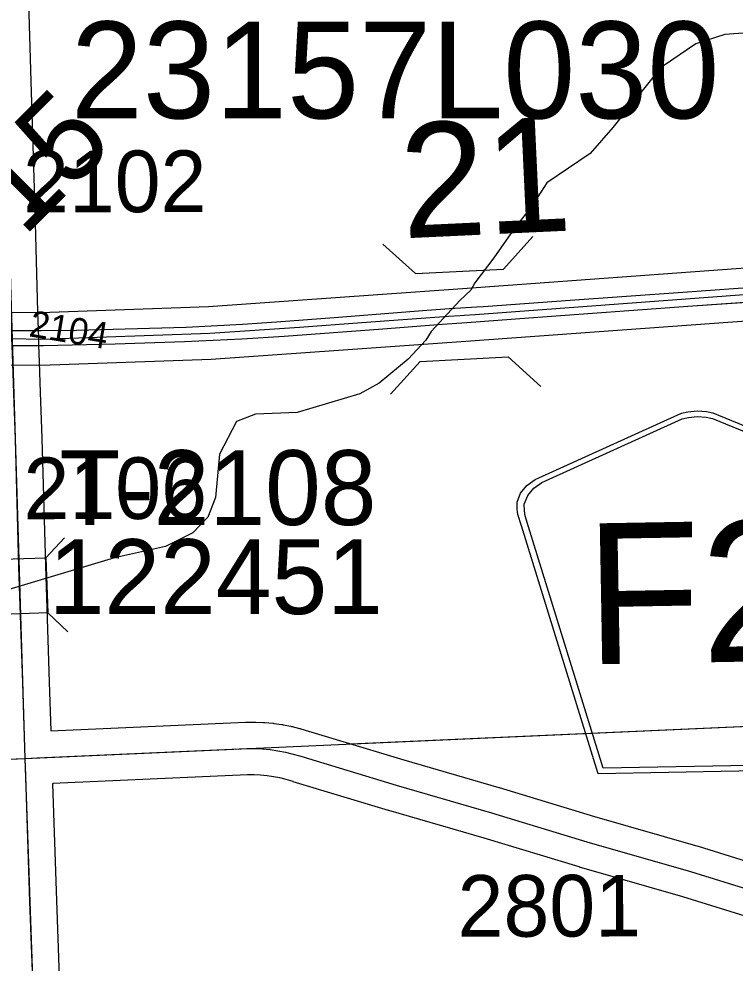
# Model space of a CAD drawing. Extents: x 128.7 to 185.5, y -21.4 to 12.6.
# Drawn here: x 154.302 to 155.116, y -11.291 to -10.218 of the extents above; entities that cross this region are included whole.
import ezdxf

# ---------------------------------------------------------------- set-up
doc = ezdxf.new("R2010")
doc.units = 0
for name, color, linetype in [('tdCoDivCarto', 7, 'Continuous'), ('tdCoHydroRiver', 7, 'Continuous'), ('tdCoPriCL', 7, 'Continuous'), ('tdCoPriDiv', 7, 'Continuous'), ('tdCoPrimary', 7, 'Continuous'), ('tdCoSecRdNmbr', 7, 'Continuous'), ('tdCoSecRteBand', 7, 'Continuous'), ('tdCoSecRteCL', 7, 'Continuous'), ('tdCoSectLine', 7, 'Continuous'), ('tdCoSectLinePart', 7, 'Continuous'), ('tdCoSectNmbr', 7, 'Continuous'), ('tdCoShieldCoRte', 7, 'Continuous'), ('tdCoStrucDivPri', 7, 'Continuous'), ('tdCoStrucPriMaintName', 7, 'Continuous'), ('tdCoStrucSec', 7, 'Continuous'), ('tdCoStrucSecCoName', 7, 'Continuous'), ('tdCoStrucSecFHWANum', 7, 'Continuous'), ('tdCoSurfAsphalt', 7, 'Continuous'), ('tdCoSurfGravel', 7, 'Continuous'), ('tdStHwyPriRefPost1', 7, 'Continuous'), ('tdStHwyPriRefPost5', 7, 'Continuous')]:
    doc.layers.add(name, color=color, linetype=linetype)

msp = doc.modelspace()

# ---------------------------------------------------------------- linework, layer by layer
at = {"layer": 'tdCoDivCarto'}
for p, q in [((155.0563, -10.5289), (154.9283, -10.538)), ((155.1189, -10.5245), (155.0563, -10.5289)), ((154.9283, -10.538), (154.8299, -10.5452)), ((155.0673, -10.5444), (155.1485, -10.5385)), ((154.7656, -10.5496), (154.6603, -10.5577)), ((154.7914, -10.5478), (154.7656, -10.5496)), ((154.8222, -10.5457), (154.7914, -10.5478)), ((154.8299, -10.5452), (154.8222, -10.5457)), ((154.8814, -10.5577), (155.0673, -10.5444)), ((154.5947, -10.5627), (154.5562, -10.5656)), ((154.6603, -10.5577), (154.5947, -10.5627)), ((154.7831, -10.5652), (154.8111, -10.5631)), ((154.8111, -10.5631), (154.8814, -10.5577)), ((154.3275, -10.5725), (154.2942, -10.5726)), ((154.3275, -10.5725), (154.2942, -10.5726)), ((154.3678, -10.5723), (154.3275, -10.5725)), ((154.4921, -10.5688), (154.3678, -10.5723)), ((154.5562, -10.5656), (154.4921, -10.5688)), ((154.6035, -10.5785), (154.7154, -10.5703)), ((154.7154, -10.5703), (154.7831, -10.5652)), ((154.4116, -10.5873), (154.4905, -10.5849)), ((154.4905, -10.5849), (154.5554, -10.5817)), ((154.5554, -10.5817), (154.6035, -10.5785)), ((154.2948, -10.5893), (154.3275, -10.5893)), ((154.2948, -10.5893), (154.3275, -10.5893)), ((154.3275, -10.5893), (154.3302, -10.5893)), ((154.3302, -10.5893), (154.4116, -10.5873))]:
    msp.add_line(p, q, dxfattribs=at)
for points in [[(155.4926, -10.4959), (155.4839, -10.4966), (155.4307, -10.5003), (155.3806, -10.5042), (155.3357, -10.5082), (155.2247, -10.5163), (155.1897, -10.5198), (155.1189, -10.5245), (155.0563, -10.5289), (154.9283, -10.538), (154.8299, -10.5452), (154.8222, -10.5457), (154.7914, -10.5478), (154.7656, -10.5496), (154.6603, -10.5577), (154.5947, -10.5627), (154.5562, -10.5656), (154.4921, -10.5688), (154.3678, -10.5723), (154.3275, -10.5725)], [(155.4926, -10.4959), (155.4839, -10.4966), (155.4307, -10.5003), (155.3806, -10.5042), (155.3357, -10.5082), (155.2247, -10.5163), (155.1897, -10.5198), (155.1189, -10.5245), (155.0563, -10.5289), (154.9283, -10.538), (154.8299, -10.5452), (154.8222, -10.5457), (154.7914, -10.5478), (154.7656, -10.5496), (154.6603, -10.5577), (154.5947, -10.5627), (154.5562, -10.5656), (154.4921, -10.5688), (154.3678, -10.5723), (154.3275, -10.5725)], [(155.4926, -10.4959), (155.4839, -10.4966), (155.4307, -10.5003), (155.3806, -10.5042), (155.3357, -10.5082), (155.2247, -10.5163), (155.1897, -10.5198), (155.1189, -10.5245), (155.0563, -10.5289), (154.9283, -10.538), (154.8299, -10.5452), (154.8222, -10.5457), (154.7914, -10.5478), (154.7656, -10.5496), (154.6603, -10.5577), (154.5947, -10.5627), (154.5562, -10.5656), (154.4921, -10.5688), (154.3678, -10.5723), (154.3275, -10.5725)], [(154.3275, -10.5893), (154.3302, -10.5893), (154.4116, -10.5873), (154.4905, -10.5849), (154.5554, -10.5817), (154.6035, -10.5785), (154.7154, -10.5703), (154.7831, -10.5652), (154.8111, -10.5631), (154.8814, -10.5577), (155.0673, -10.5444), (155.1485, -10.5385), (155.2893, -10.5274), (155.4414, -10.5161), (155.4939, -10.5119)], [(154.3275, -10.5893), (154.3302, -10.5893), (154.4116, -10.5873), (154.4905, -10.5849), (154.5554, -10.5817), (154.6035, -10.5785), (154.7154, -10.5703), (154.7831, -10.5652), (154.8111, -10.5631), (154.8814, -10.5577), (155.0673, -10.5444), (155.1485, -10.5385), (155.2893, -10.5274), (155.4414, -10.5161), (155.4939, -10.5119)], [(154.3275, -10.5893), (154.3302, -10.5893), (154.4116, -10.5873), (154.4905, -10.5849), (154.5554, -10.5817), (154.6035, -10.5785), (154.7154, -10.5703), (154.7831, -10.5652), (154.8111, -10.5631), (154.8814, -10.5577), (155.0673, -10.5444), (155.1485, -10.5385), (155.2893, -10.5274), (155.4414, -10.5161), (155.4939, -10.5119)], [(154.3275, -10.5725), (154.2942, -10.5726)], [(154.3275, -10.5725), (154.2942, -10.5726)], [(154.2948, -10.5893), (154.3275, -10.5893)], [(154.2948, -10.5893), (154.3275, -10.5893)]]:
    msp.add_lwpolyline(points, dxfattribs=at)
at = {"layer": 'tdCoHydroRiver'}
msp.add_lwpolyline([(155.1401, -10.2333), (155.1039, -10.2362), (155.0711, -10.2468), (155.0341, -10.2718), (155.022, -10.2849), (154.9767, -10.3417), (154.9509, -10.3711), (154.9016, -10.4044), (154.8847, -10.431), (154.8661, -10.4545), (154.8415, -10.4896), (154.8199, -10.5181), (154.8153, -10.5264), (154.8028, -10.5383), (154.7704, -10.5734), (154.7643, -10.5832), (154.7442, -10.6049), (154.7115, -10.632), (154.6896, -10.6443), (154.6184, -10.6655), (154.5711, -10.6671), (154.5493, -10.6757), (154.5301, -10.7127), (154.5255, -10.7618), (154.5168, -10.7842), (154.5, -10.8021), (154.469, -10.8174), (154.411, -10.8304), (154.286, -10.8678)], dxfattribs=at)
at = {"layer": 'tdCoPriCL'}
msp.add_lwpolyline([(153.0442, -10.649), (153.1163, -10.643), (153.1776, -10.6373), (153.2928, -10.6269), (153.3089, -10.6255), (153.3454, -10.6224), (153.5843, -10.6023), (153.6845, -10.5941), (153.9006, -10.5841), (154.0396, -10.5816), (154.0415, -10.5816), (154.0437, -10.5816), (154.0641, -10.5812), (154.2274, -10.5809), (154.2935, -10.5813), (154.3272, -10.582), (154.519, -10.5753), (154.621, -10.5686), (154.6919, -10.5631), (154.79, -10.556), (154.8035, -10.5551), (154.8079, -10.5548), (154.8203, -10.5539), (155.2987, -10.5184)], dxfattribs=at)
at = {"layer": 'tdCoPriDiv'}
for points in [[(156.3051, -10.3234), (156.1332, -10.3967), (156.0515, -10.4224), (155.9864, -10.4355), (155.5871, -10.4668), (155.5413, -10.4713), (154.8061, -10.5249), (154.5175, -10.5454), (154.327, -10.552), (154.0638, -10.5512), (153.8996, -10.5541), (153.6825, -10.5641), (153.3063, -10.5956), (153.0365, -10.6196)], [(156.3288, -10.3785), (156.1544, -10.4529), (156.0668, -10.4804), (155.9958, -10.4947), (155.5922, -10.5266), (155.5457, -10.5312), (154.8098, -10.5848), (154.5205, -10.6053), (154.3274, -10.612), (154.0644, -10.6112), (153.9015, -10.6141), (153.6864, -10.624), (153.3115, -10.6554), (153.0414, -10.6794)]]:
    msp.add_lwpolyline(points, dxfattribs=at)
at = {"layer": 'tdCoPrimary'}
for p, q in [((154.3275, -10.5725), (154.2942, -10.5726)), ((154.3275, -10.5725), (154.2942, -10.5726)), ((154.2948, -10.5893), (154.3275, -10.5893)), ((154.2948, -10.5893), (154.3275, -10.5893))]:
    msp.add_line(p, q, dxfattribs=at)
for points in [[(155.4926, -10.4959), (155.4839, -10.4966), (155.4307, -10.5003), (155.3806, -10.5042), (155.3357, -10.5082), (155.2247, -10.5163), (155.1897, -10.5198), (155.1189, -10.5245), (155.0563, -10.5289), (154.9283, -10.538), (154.8299, -10.5452), (154.8222, -10.5457), (154.7914, -10.5478), (154.7656, -10.5496), (154.6603, -10.5577), (154.5947, -10.5627), (154.5562, -10.5656), (154.4921, -10.5688), (154.3678, -10.5723), (154.3275, -10.5725)], [(155.4926, -10.4959), (155.4839, -10.4966), (155.4307, -10.5003), (155.3806, -10.5042), (155.3357, -10.5082), (155.2247, -10.5163), (155.1897, -10.5198), (155.1189, -10.5245), (155.0563, -10.5289), (154.9283, -10.538), (154.8299, -10.5452), (154.8222, -10.5457), (154.7914, -10.5478), (154.7656, -10.5496), (154.6603, -10.5577), (154.5947, -10.5627), (154.5562, -10.5656), (154.4921, -10.5688), (154.3678, -10.5723), (154.3275, -10.5725)], [(154.3275, -10.5893), (154.3302, -10.5893), (154.4116, -10.5873), (154.4905, -10.5849), (154.5554, -10.5817), (154.6035, -10.5785), (154.7154, -10.5703), (154.7831, -10.5652), (154.8111, -10.5631), (154.8814, -10.5577), (155.0673, -10.5444), (155.1485, -10.5385), (155.2893, -10.5274), (155.4414, -10.5161), (155.4939, -10.5119)], [(154.3275, -10.5893), (154.3302, -10.5893), (154.4116, -10.5873), (154.4905, -10.5849), (154.5554, -10.5817), (154.6035, -10.5785), (154.7154, -10.5703), (154.7831, -10.5652), (154.8111, -10.5631), (154.8814, -10.5577), (155.0673, -10.5444), (155.1485, -10.5385), (155.2893, -10.5274), (155.4414, -10.5161), (155.4939, -10.5119)], [(155.1189, -10.5245), (155.0563, -10.5289), (154.9283, -10.538), (154.8299, -10.5452), (154.8222, -10.5457), (154.7914, -10.5478), (154.7656, -10.5496), (154.6603, -10.5577), (154.5947, -10.5627), (154.5562, -10.5656), (154.4921, -10.5688), (154.3678, -10.5723), (154.3275, -10.5725), (154.2942, -10.5726)], [(154.2948, -10.5893), (154.3275, -10.5893), (154.3302, -10.5893), (154.4116, -10.5873), (154.4905, -10.5849), (154.5554, -10.5817), (154.6035, -10.5785), (154.7154, -10.5703), (154.7831, -10.5652), (154.8111, -10.5631), (154.8814, -10.5577), (155.0673, -10.5444), (155.1485, -10.5385)]]:
    msp.add_lwpolyline(points, dxfattribs=at)
at = {"layer": 'tdCoSecRteBand'}
for points in [[(154.3114, -10.1355), (154.3161, -10.2891), (154.3161, -10.2891), (154.3161, -10.2891), (154.3203, -10.4356), (154.3203, -10.4356), (154.3203, -10.4356), (154.3235, -10.5509), (154.3242, -10.5715), (154.3245, -10.5802), (154.3248, -10.5883), (154.3255, -10.6081), (154.3255, -10.6082), (154.3255, -10.6082), (154.3255, -10.6082), (154.3267, -10.6428), (154.3267, -10.6428), (154.3267, -10.6428), (154.3284, -10.6946), (154.3284, -10.6947), (154.3284, -10.6948), (154.3324, -10.8397), (154.3368, -10.9716), (154.3368, -10.9716), (154.3368, -10.9716), (154.3386, -11.0269), (154.5598, -11.0171), (154.5604, -11.0171), (154.5609, -11.0171), (154.5698, -11.017), (154.5706, -11.017), (154.5713, -11.017), (154.5802, -11.0174), (154.5809, -11.0174), (154.5817, -11.0175), (154.5905, -11.0183), (154.5913, -11.0184), (154.592, -11.0185), (154.6008, -11.0198), (154.6016, -11.0199), (154.6023, -11.0201), (154.611, -11.0218), (154.6117, -11.0219), (154.6125, -11.0221), (154.6211, -11.0243), (154.6218, -11.0244), (154.6226, -11.0247), (154.631, -11.0272), (154.7393, -11.06), (154.8474, -11.0912), (154.8476, -11.0913), (154.8478, -11.0913), (154.9558, -11.1241), (155.073, -11.1578), (155.0733, -11.1579), (155.0736, -11.158), (155.1764, -11.19)], [(155.1586, -11.2473), (155.0561, -11.2154), (154.939, -11.1817), (154.9388, -11.1816), (154.9386, -11.1816), (154.8306, -11.1488), (154.7225, -11.1176), (154.7223, -11.1175), (154.7221, -11.1175), (154.6136, -11.0847), (154.6136, -11.0846), (154.6136, -11.0846), (154.6058, -11.0823), (154.5987, -11.0805), (154.5914, -11.0791), (154.5842, -11.078), (154.5768, -11.0773), (154.5695, -11.077), (154.5619, -11.0771), (154.3408, -11.0869), (154.3408, -11.087), (154.3406, -11.087), (154.3449, -11.2196), (154.3494, -11.3389)]]:
    msp.add_lwpolyline(points, dxfattribs=at)
at = {"layer": 'tdCoSecRteCL'}
for points in [[(154.3096, -11.0582), (154.3068, -10.9726), (154.3024, -10.8407), (154.2984, -10.6956), (154.2967, -10.6438), (154.2955, -10.6092), (154.2955, -10.6092), (154.2948, -10.5893), (154.2945, -10.5813), (154.2942, -10.5726), (154.2935, -10.5518), (154.2903, -10.4365), (154.2861, -10.29), (154.2814, -10.1363)], [(154.3096, -11.0582), (154.3227, -11.0577), (154.5611, -11.0471), (154.57, -11.047), (154.5789, -11.0474), (154.5877, -11.0482), (154.5965, -11.0495), (154.6052, -11.0512), (154.6138, -11.0534), (154.6223, -11.0559), (154.7308, -11.0887), (154.8391, -11.1201), (154.9473, -11.1529), (155.0647, -11.1866), (155.1676, -11.2187), (155.2541, -11.2448), (155.3779, -11.2865), (155.4973, -11.3319), (155.5707, -11.3589)], [(152.8081, -11.1262), (152.8426, -11.125), (153.0322, -11.1154), (153.1888, -11.1085), (153.3989, -11.0996), (153.5626, -11.0922), (153.6793, -11.0865), (153.9002, -11.0764), (154.0946, -11.0673), (154.2679, -11.0599), (154.3096, -11.0582)], [(154.3194, -11.34), (154.3149, -11.2207), (154.3103, -11.0784), (154.3096, -11.0582)]]:
    msp.add_lwpolyline(points, dxfattribs=at)
at = {"layer": 'tdCoSectLine'}
for points in [[(154.2784, -10.0557), (154.3092, -11.0582)], [(154.3092, -11.0582), (155.3093, -11.0137)], [(153.309, -11.1034), (154.3092, -11.0582)], [(154.3092, -11.0582), (154.3445, -12.0662)]]:
    msp.add_lwpolyline(points, dxfattribs=at)
at = {"layer": 'tdCoSectLinePart'}
msp.add_lwpolyline([(154.6783, -11.0418), (155.3093, -11.0137)], dxfattribs=at)
at = {"layer": 'tdCoShieldCoRte'}
for points in [[(154.9599, -11.0756), (154.873, -10.7942), (154.8689, -10.7811), (154.8681, -10.7752), (154.8679, -10.7674), (154.872, -10.757), (154.8791, -10.7484), (154.8886, -10.7416), (155.0546, -10.6663), (155.062, -10.6645), (155.0725, -10.6634), (155.0829, -10.6642), (155.0904, -10.6657), (155.2589, -10.7351), (155.2686, -10.7416), (155.2761, -10.75), (155.2805, -10.7602), (155.2806, -10.768), (155.28, -10.7739), (155.2763, -10.7871), (155.1994, -11.0714)], [(154.9656, -11.0692), (154.8811, -10.7953), (154.8771, -10.7828), (154.8764, -10.7771), (154.8762, -10.7696), (154.8801, -10.7596), (154.887, -10.7514), (154.896, -10.7448), (155.0554, -10.6726), (155.0626, -10.6709), (155.0726, -10.6698), (155.0826, -10.6705), (155.0898, -10.672), (155.2516, -10.7386), (155.2609, -10.7448), (155.268, -10.7529), (155.2723, -10.7627), (155.2724, -10.7702), (155.2718, -10.7759), (155.2683, -10.7886), (155.1934, -11.0652)]]:
    msp.add_lwpolyline(points, close=True, dxfattribs=at)
at = {"layer": 'tdCoStrucDivPri'}
for points in [[(154.7155, -10.4741), (154.7526, -10.5076), (154.8525, -10.5025), (154.886, -10.4653)], [(154.7243, -10.6446), (154.7578, -10.6075), (154.8577, -10.6023), (154.8948, -10.6358)]]:
    msp.add_lwpolyline(points, dxfattribs=at)
at = {"layer": 'tdCoStrucSec'}
for p, q in [((154.333, -10.8304), (154.3543, -10.8076)), ((154.3351, -10.893), (154.3579, -10.9144))]:
    msp.add_line(p, q, dxfattribs=at)
msp.add_lwpolyline([(154.2725, -10.8951), (154.2704, -10.8325), (154.333, -10.8304), (154.3351, -10.893)], close=True, dxfattribs=at)
at = {"layer": 'tdCoSurfAsphalt'}
for points in [[(154.3096, -11.0582), (154.3068, -10.9726), (154.3024, -10.8407), (154.2984, -10.6956), (154.2967, -10.6438), (154.2955, -10.6092), (154.2955, -10.6092), (154.2948, -10.5893), (154.2945, -10.5813)], [(152.5527, -11.146), (152.5592, -11.1418), (152.5703, -11.1376), (152.6423, -11.1321), (152.7651, -11.1277), (152.8081, -11.1262), (152.8426, -11.125), (153.0322, -11.1154), (153.1888, -11.1085), (153.3989, -11.0996), (153.5626, -11.0922), (153.6793, -11.0865), (153.9002, -11.0764), (154.0946, -11.0673), (154.2679, -11.0599), (154.3096, -11.0582)], [(154.3368, -11.8277), (154.3354, -11.7817), (154.3293, -11.6318), (154.3241, -11.4882), (154.3194, -11.34), (154.3149, -11.2207), (154.3103, -11.0784), (154.3096, -11.0582)]]:
    msp.add_lwpolyline(points, dxfattribs=at)
at = {"layer": 'tdCoSurfGravel'}
msp.add_lwpolyline([(154.3096, -11.0582), (154.3227, -11.0577), (154.5611, -11.0471), (154.57, -11.047), (154.5789, -11.0474), (154.5877, -11.0482), (154.5965, -11.0495), (154.6052, -11.0512), (154.6138, -11.0534), (154.6223, -11.0559), (154.7308, -11.0887), (154.8391, -11.1201), (154.9473, -11.1529), (155.0647, -11.1866), (155.1676, -11.2187), (155.2541, -11.2448), (155.3779, -11.2865), (155.4973, -11.3319), (155.5707, -11.3589)], dxfattribs=at)

# ---------------------------------------------------------------- texts
at = {"layer": 'tdCoSecRdNmbr'}
for s, height, rotation, p in [('2102', 0.07, 0.1169, (154.3071, -10.4381)), ('2104', 0.03, 350.5437, (154.3128, -10.5787)), ('2106', 0.07, 0.1169, (154.3077, -10.7866)), ('2801', 0.07, 0.1164, (154.8005, -11.2609))]:
    msp.add_text(s, height=height, rotation=rotation, dxfattribs=at).set_placement(p)
at = {"layer": 'tdCoSectNmbr'}
msp.add_text('21', height=0.13, rotation=2.6696, dxfattribs=at).set_placement((154.7384, -10.4676))
at = {"layer": 'tdCoShieldCoRte'}
msp.add_text('F21', height=0.16, rotation=1, dxfattribs=at).set_placement((154.9471, -10.9515))
at = {"layer": 'tdCoStrucPriMaintName'}
msp.add_text('23157L030', height=0.11, dxfattribs=at).set_placement((154.3614, -10.3313))
msp.add_text('23157L030', height=0.11, dxfattribs=at).set_placement((154.3614, -10.3313))
msp.add_text('23157L030', height=0.11, dxfattribs=at).set_placement((154.3614, -10.3313))
at = {"layer": 'tdCoStrucSecCoName'}
msp.add_text('T-2108', height=0.085, dxfattribs=at).set_placement((154.3482, -10.7932))
at = {"layer": 'tdCoStrucSecFHWANum'}
msp.add_text('122451', height=0.085, dxfattribs=at).set_placement((154.3363, -10.8943))
at = {"layer": 'tdStHwyPriRefPost1'}
msp.add_text('‒‒315', height=0.1, rotation=45, dxfattribs=at).set_placement((154.1499, -10.6247))
at = {"layer": 'tdStHwyPriRefPost5'}
msp.add_text('‒‒315', height=0.1, rotation=45, dxfattribs=at).set_placement((154.1499, -10.6247))

doc.saveas('drawing.dxf')
